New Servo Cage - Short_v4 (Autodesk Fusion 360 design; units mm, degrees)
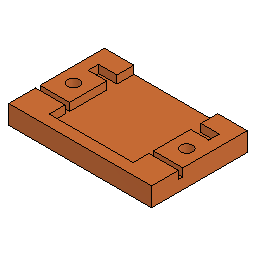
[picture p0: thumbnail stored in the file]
sketch "Sketch1" plane through (0, 0, 0) normal (0, 0, 1) x axis (1, 0, 0)
  line L1 (-14.4, -13) -> (14.4, -13)
  line L2 (-14.4, 13) -> (-14.4, -13)
  line L3 (14.4, 13) -> (-14.4, 13)
  line L4 (14.4, -13) -> (14.4, 13)
  line L5 (-14.4, 13) -> (14.4, -13)
  line L6 (14.4, 13) -> (-14.4, -13)
  line L7 (20.788, 7) -> (-24.9538, 7)
  line L8 (0, 13) -> (0, 0)
  line L9 (-19.4, 5.6) -> (19.4, 5.6)
  line L10 (-19.4, 8.4) -> (-19.4, 5.6)
  line L11 (19.4, 8.4) -> (-19.4, 8.4)
  line L12 (19.4, 5.6) -> (19.4, 8.4)
  line L13 (-19.4, 8.4) -> (19.4, 5.6)
  line L14 (19.4, 8.4) -> (-19.4, 5.6)
  line L15 (19.4, 5.6) -> (-19.4, 5.6)
  line L16 (19.4, 0.6) -> (19.4, 5.6)
  line L17 (-19.4, 0.6) -> (19.4, 0.6)
  line L18 (-19.4, 5.6) -> (-19.4, 0.6)
  line L19 (-19.4, 0) -> (0, 0)
  line L20 (19.4, 8.4) -> (-19.4, 8.4)
  line L21 (19.4, 11.4) -> (19.4, 8.4)
  line L22 (-19.4, 11.4) -> (19.4, 11.4)
  line L23 (-19.4, 8.4) -> (-19.4, 11.4)
  line L24 (-16.4, 0.6) -> (-16.4, 11.4)
  line L25 (16.4, 0.6) -> (16.4, 11.4)
  line L26 (11.4, 13) -> (-11.4, 13)
  line L27 (11.4, -10) -> (11.4, 13)
  line L28 (-11.4, -10) -> (11.4, -10)
  line L29 (-11.4, 13) -> (-11.4, -10)
  line L30 (-19.4, -13) -> (19.4, -13)
  line L31 (-19.4, 13) -> (-19.4, -13)
  line L32 (19.4, 13) -> (-19.4, 13)
  line L33 (19.4, -13) -> (19.4, 13)
  line L34 (-19.4, 13) -> (19.4, -13)
  line L35 (19.4, 13) -> (-19.4, -13)
  line L36 (19.4, -5.1) -> (-19.4, -5.1)
  line L37 (-19.4, -5.7) -> (19.4, -5.7)
  line L38 (-19.4, -4.5) -> (-19.4, -5.7)
  line L39 (19.4, -4.5) -> (-19.4, -4.5)
  line L40 (19.4, -5.7) -> (19.4, -4.5)
  line L41 (-19.4, -4.5) -> (19.4, -5.7)
  line L42 (19.4, -4.5) -> (-19.4, -5.7)
  line L43 (16.4, -13) -> (16.4, 0.6)
  line L44 (-16.4, -13) -> (-16.4, 0.6)
  circle C1 centre (-15.4, 0.6) radius 1.6
  circle C2 centre (15.4, 0.6) radius 1.6
  point P6 (0, 0)
  point P1 (0, 0)
  point P9 (0, 0)
  point P10 (0, 13)
  point P15 (0, 7)
  point P19 (-19.4, 0)
  point P23 (-16.4, 11.4)
  point P24 (-16.4, 0.6)
  point P25 (16.4, 11.4)
  point P26 (16.4, 0.6)
  point P27 (-11.4, 13)
  point P35 (0, 0)
  point P36 (-19.4, -5.1)
  point P37 (19.4, -5.1)
  point P42 (0, -5.1)
  point P43 (16.4, -13)
  point P44 (-16.4, -13)
  point P45 (-15.4, 0.6)
  point P3 (-14.4, -13)
  point P4 (-14.4, 13)
  point P2 (14.4, -13)
  point P13 (-19.4, 8.4)
  point P14 (19.4, 8.4)
  point P12 (-19.4, 5.6)
  point P18 (-19.4, 0.6)
  point P17 (19.4, 0.6)
  point P22 (-19.4, 11.4)
  point P21 (19.4, 11.4)
  point P28 (11.4, 13)
  point P30 (-11.4, -10)
  point P33 (-19.4, 13)
  point P34 (19.4, 13)
  point P32 (-19.4, -13)
  point P40 (-19.4, -4.5)
  point P41 (19.4, -4.5)
  point P39 (-19.4, -5.7)
  horizontal L1
  perpendicular L1 L2
  parallel L1 L3
  parallel L2 L4
  coincident L5 P6
  coincident L6 P6
  coincident P1 P6
  perpendicular L4 L7
  coincident P6 P9
  midpoint L3 P10
  horizontal L9
  perpendicular L9 L10
  parallel L9 L11
  parallel L10 L12
  coincident L13 P15
  coincident L14 P15
  coincident L7 P15
  coincident L8 P15
  horizontal L15
  vertical L16
  horizontal L17
  vertical L18
  coincident L18 P19
  perpendicular L18 L19
  horizontal L20
  vertical L21
  horizontal L22
  vertical L23
  coincident L22 P23
  coincident L17 P24
  perpendicular L17 L24
  symmetric L8 P23 P25
  symmetric L8 P24 P26
  horizontal L26
  vertical L27
  horizontal L28
  vertical L29
  coincident L3 P27
  horizontal L30
  perpendicular L30 L31
  parallel L30 L32
  parallel L31 L33
  coincident L34 P35
  coincident L35 P35
  coincident P9 P35
  coincident L31 P36
  coincident L33 P37
  perpendicular L33 L36
  horizontal L37
  perpendicular L37 L38
  parallel L37 L39
  parallel L38 L40
  coincident L41 P42
  coincident L42 P42
  midpoint L36 P42
  coincident L30 P43
  perpendicular L30 L43
  coincident L30 P44
  perpendicular L30 L44
  coincident L17 P45
  symmetric L8 C1 C2
  dimension "d1" distance P3 P4 = 26 (= "23 mm + 3 mm")
  dimension "d2" distance P2 P3 = 28.8 (= "22.8 mm + 6 mm")
  dimension "d3" distance L1 L7 = 20 (= "15.6 mm + d5 / 2 + 3 mm")
  dimension "d4" distance P13 P14 = 38.8 (= "d2 + 10 mm")
  dimension "d5" distance P12 P13 = 2.8
  dimension "d6" distance P12 P18 = 5
  dimension "d7" distance P17 P18 = 38.8 (= "d4")
  dimension "d13" distance P13 P22 = 3
  dimension "d14" distance P21 P22 = 38.8 (= "d4")
  dimension "d15" distance L18 L24 = 3
  dimension "d16" distance P27 P28 = 22.8
  dimension "d17" distance P27 P30 = 23
  dimension "d18" distance L2 L29 = 3
  dimension "d25" distance P33 P34 = 38.8 (= "d4")
  dimension "d26" distance P32 P33 = 26 (= "d1")
  dimension "d29" distance L28 L36 = 4.9 (= "4.4 mm + ( 1 / 2 ) * 1 mm")
  dimension "d30" distance P40 P41 = 38.8 (= "d4")
  dimension "d31" distance P39 P40 = 1.2
  dimension "d33" diameter C1 = 3.2
  dimension "d34" distance L31 P45 = 4
extrude "Extrude1" new body sketch "Sketch1" profile of L1 L2 L3 L4 L9 L10 L11 L12 L15 L16 L17 L18 L20 L21 L22 L23 L24 L25 L27 L28 L29 L30 L31 L32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 along normal blind 5.15 (= "( ( 12.3 / 2 ) * 1 mm ) + 3 mm - 4 mm")
extrude "Extrude2" add sketch "Sketch1" profile of L2 L3 L4 L9 L11 L15 L17 L20 L22 L24 L25 L26 L27 L28 L29 L31 L32 L33 L37 L38 L39 L40 L43 L44 along normal blind 3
